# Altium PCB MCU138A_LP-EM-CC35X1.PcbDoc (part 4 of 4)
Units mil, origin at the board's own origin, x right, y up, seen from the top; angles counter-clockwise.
Board outline 2309.44 x 2672.36 mil, 4 copper layers (Top Layer, L02_GND, L03_PWR, Bottom Layer), stack 60 mil thick; 235 components, 167 nets, 678 pads, 887 vias.
Unrouted connection lines stored in the file: 19.
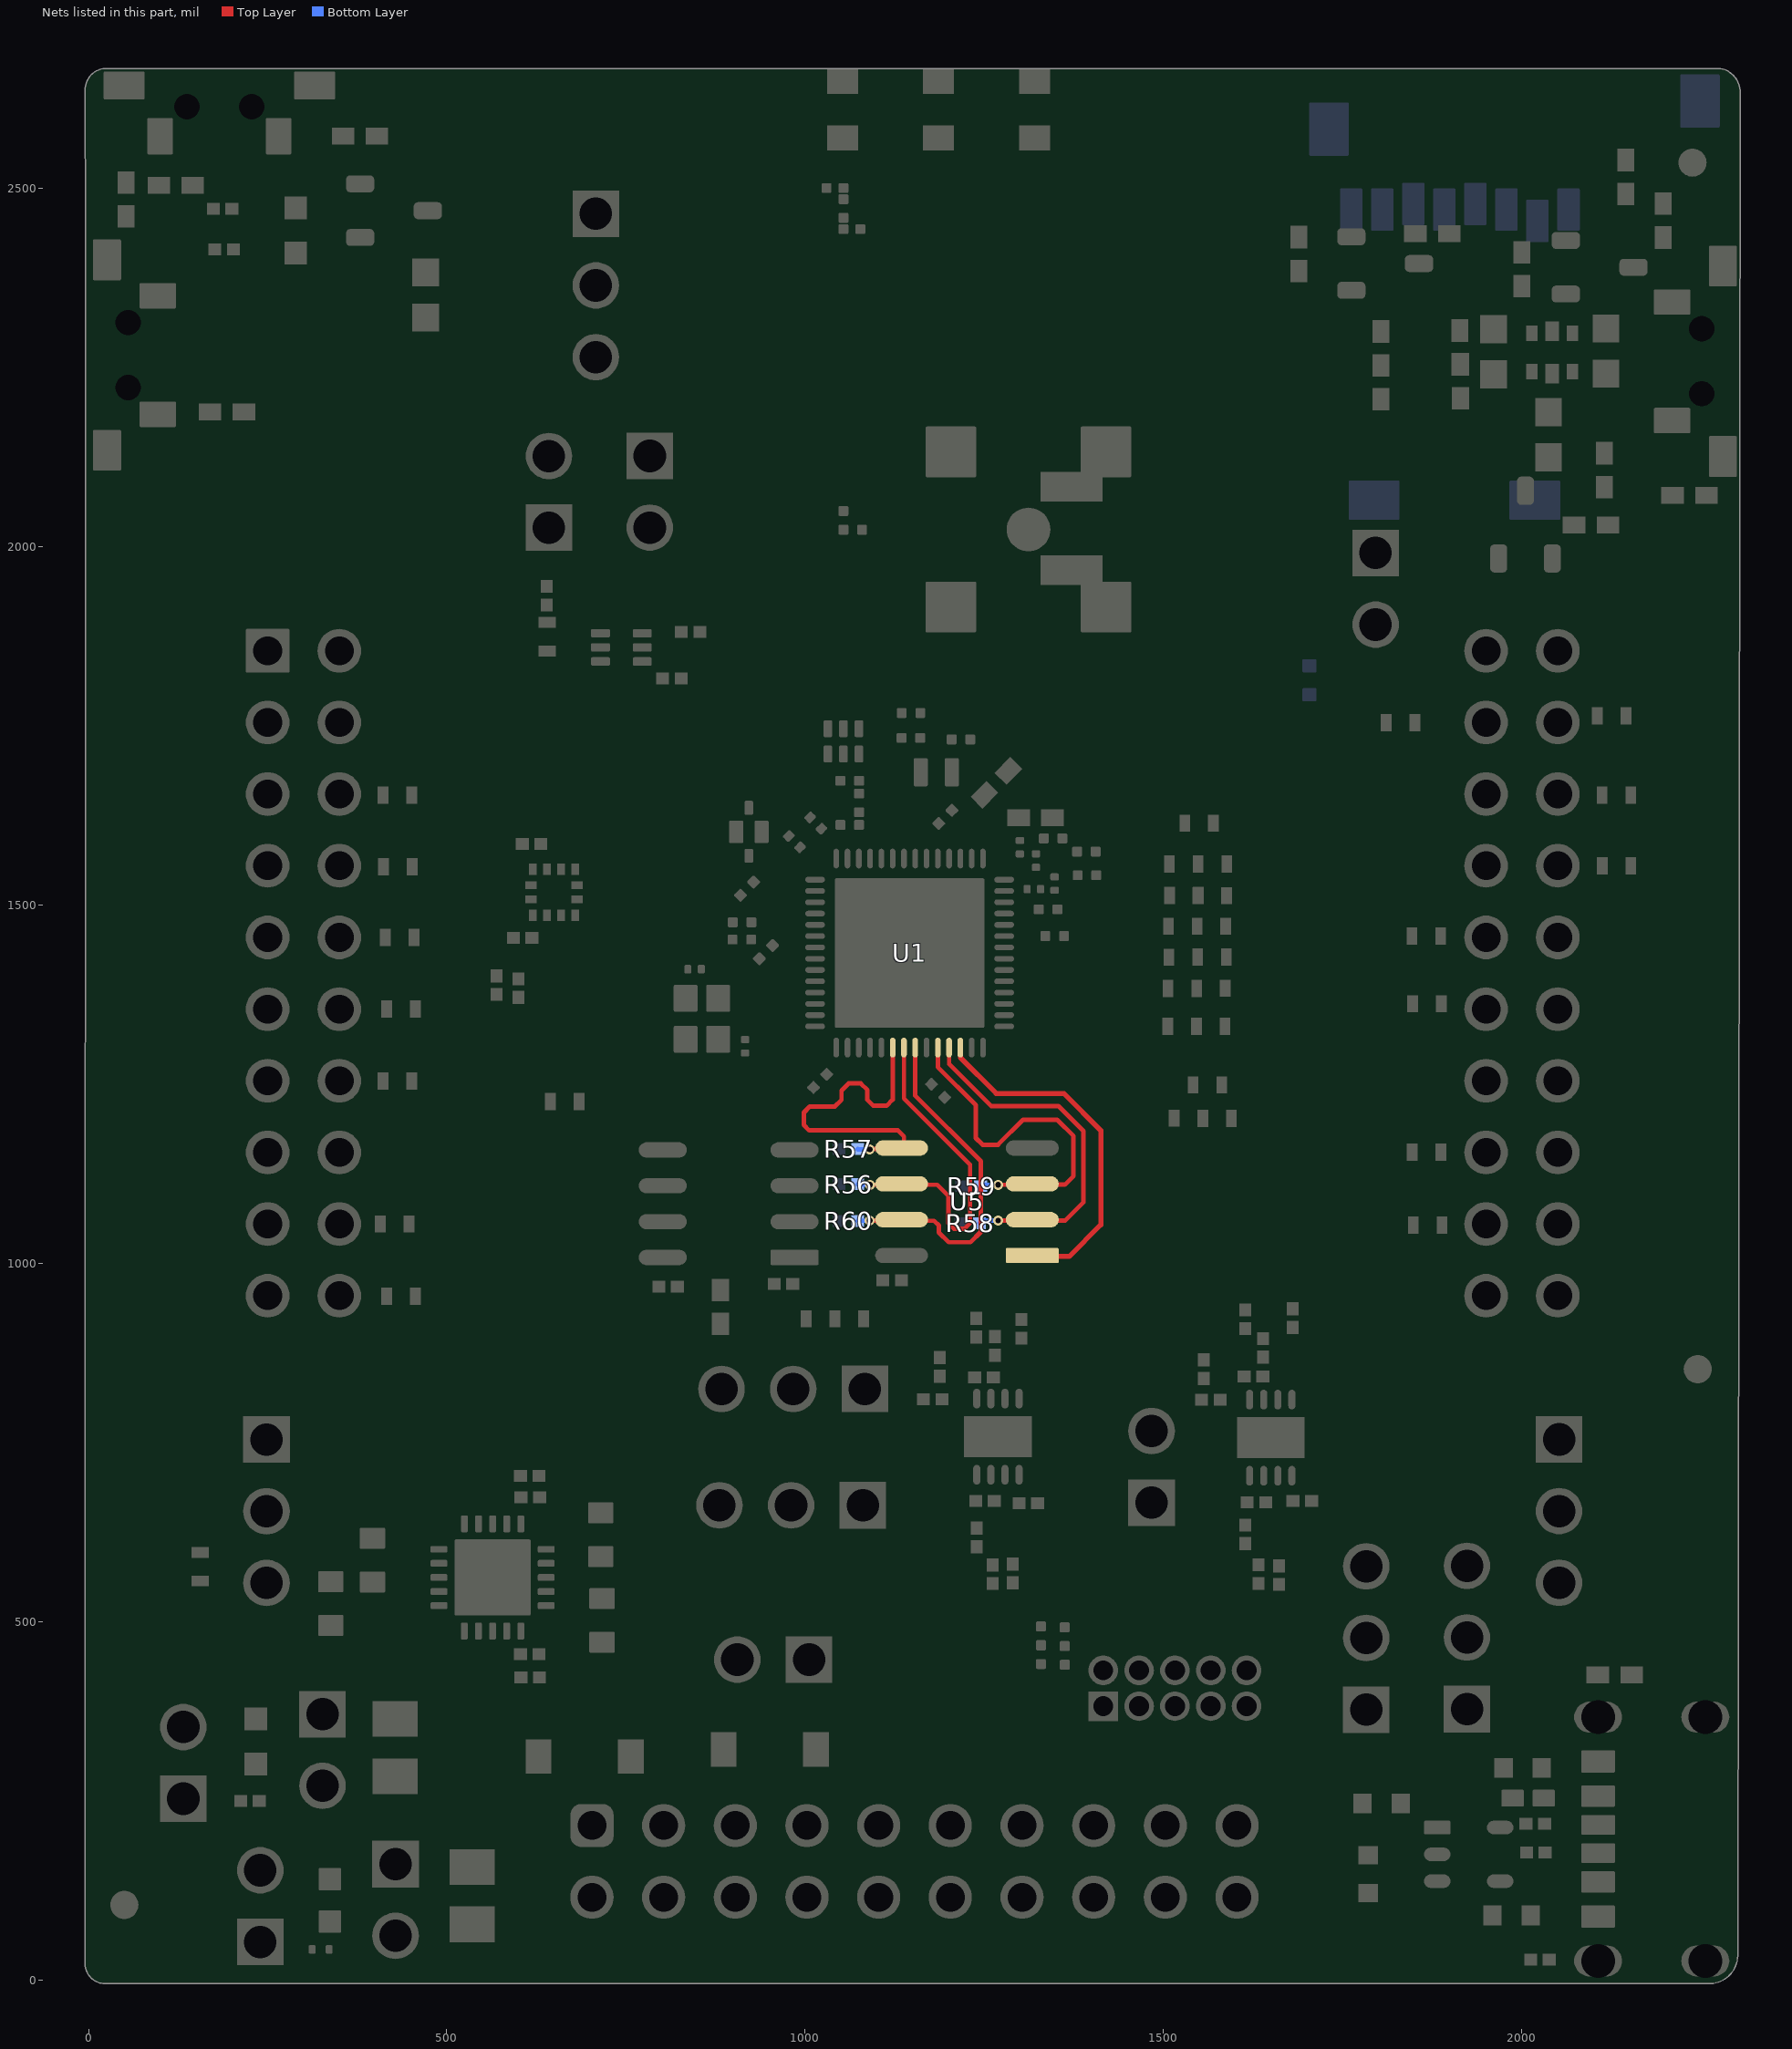
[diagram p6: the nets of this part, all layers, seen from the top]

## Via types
v1: diameter 14, hole 7.87, Top Layer to Bottom Layer, tented both sides, 816 vias
v2: diameter 19.68, hole 7.87, Top Layer to Bottom Layer, tented both sides, 25 vias
v3: diameter 14, hole 8, Top Layer to Bottom Layer, tented both sides, 19 vias
v4: diameter 24, hole 12, Top Layer to Bottom Layer, tented both sides, 14 vias
v5: diameter 19.68, hole 7.87, Top Layer to Bottom Layer, 13 vias

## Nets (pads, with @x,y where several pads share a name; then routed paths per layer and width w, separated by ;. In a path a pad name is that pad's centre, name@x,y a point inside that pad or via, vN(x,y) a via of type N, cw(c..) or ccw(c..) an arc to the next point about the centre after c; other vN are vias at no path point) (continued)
xSPI_CLK: R56.1 U1.21 U5.6 | length 489
  Top Layer w6.17: v1@1093,1109.71 1137.89,1109.71 1184.3,1109.71 1199.98,1094.03 1199.98,1055.81 1207.6,1048.19 1222.03,1048.19 1230.15,1056.31 1230.15,1137.88 1137.8,1230.22 U1.21@1137.8,1301.19
  Bottom Layer w6.17: R56.1@1073.16,1110.41 1073.5,1110.07 1090.07,1110.07 v1(1090.41,1109.73)
xSPI_CS_FLASH: U1.26 U5.1 | length 494.3
  Top Layer w7: U1.26@1216.54,1301.19 1216.54,1287.25 1266.64,1237.15 1360.89,1237.15 1412.58,1185.45 1412.58,1053.94 1368.36,1009.71 U5.1@1320.26,1009.71
xSPI_D0: R57.1 U1.20 U5.5 | length 489
  Top Layer w6.17: v1@1093,1159.71 1137.89,1159.71 1137.89,1177.3 1129.53,1185.66 1005.75,1185.66 998.14,1193.26 998.14,1210.64 1006.36,1218.86 1041.36,1218.86 1050.58,1228.08 1050.58,1241.17 1060.56,1251.15 1077.66,1251.15 1086.69,1242.12 1086.69,1228.32 1095.04,1219.97 1113.54,1219.97 1122.05,1228.48 U1.20@1122.05,1301.19
  Bottom Layer w6.17: R57.1@1073.15,1159.51 1073.4,1159.27 1089.86,1159.27 v1(1090.11,1159.02)
xSPI_D1: R58.1 U1.25 U5.2 | length 505.1
  Top Layer w6.17: U1.25@1200.79,1301.19 1200.79,1278.22 1259.41,1219.61 1353.22,1219.61 1388.3,1184.52 1388.3,1085.4 1362.86,1059.97 1320.52,1059.97 1320.26,1059.71 v1(1269.02,1059.71)
  Bottom Layer w6.17: R58.1@1243.14,1056.31 cw(c1251.36,1048.09) 1251.36,1059.71 v1(1269.02,1059.71)
xSPI_D2: R59.1 U1.24 U5.3 | length 502.9
  Top Layer w6.17: U1.24@1185.05,1301.19 1185.05,1273.92 1238.04,1220.92 1238.04,1175.02 1247.54,1165.52 1269.05,1165.52 1303.93,1200.4 1351.49,1200.4 1374.27,1177.62 1374.27,1122.07 1362.17,1109.96 1320.51,1109.96 1320.26,1109.71 v1(1269.02,1109.71)
  Bottom Layer w6.17: R59.1@1244.75,1107.86 cw(c1249.22,1103.4) 1249.22,1109.71 v1(1269.02,1109.71)
xSPI_D3: R60.1 U1.22 U5.7 | length 488.1
  Top Layer w6.17: v1@1093,1059.71 1137.89,1059.71 1138.05,1059.55 1179.89,1059.55 1186.48,1052.97 1186.48,1043.22 1200.13,1029.57 1230.64,1029.57 1245.02,1043.95 1245.02,1142.62 1153.55,1234.09 U1.22@1153.55,1301.19
  Bottom Layer w6.17: R60.1@1073.42,1059.43 1073.58,1059.59 1089.93,1059.59 v1(1090.09,1059.75)
pads on no net: E1.2 E1.3 E1.4 E1.5 FID1.1 FID2.1 FID3.1 J2.2@1371.62,2084.59 J2.3@1371.62,1966.48 J3.10 J7.2 J7.3 J7.4 J7.5 J7.9 J22.6 J22.8 LBL1.0 S1. SH-J1.0 SH-J2.0 SH-J3.0 SH-J4.0 SH-J5.0 SH-J6.0 SH-J7.0 SH-J8.0 SH-J9.0 SH-J10.0 SH-J11.0 SH-J12.0 SH-J13.0 SH-J14.0 SW1. SW2. U2.7 U2.9 U2.17 U2.19 U2.21A U2.21B U2.21C U2.21D U8.3 U9.4 U9.5 U9.6 U9.11

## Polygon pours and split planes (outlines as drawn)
GND on Top Layer "TOP_LAYER_GND_P000" (solid, remove dead copper, pour order 0): 22.54,2667.32 2277.75,2666.89 cw(c2273.98,2636.17) 2304.69,2632.31 2301.28,30.28 cw(c2258.62,38.22) 2262.2,-5.02 22.54,-5.05 cw(c23.83,23.48) -4.7,24.75 -4.43,2634.94 cw(c25.18,2637.7)
VDD_PA on L03_PWR "L03_PWR_VDD_PA_P024" (solid, remove dead copper, pour order 24): 89.12,323.4 335.95,323.4 ccw(c335.95,369.29) 381.84,369.29 381.84,1180.26 691.81,1490.22 1032.34,1490.22 1078.11,1535.99 1078.11,1641.26 995.79,1723.58 108.39,1723.58 89.12,1704.31
GND on L03_PWR "L03_PWR_GND_P035" (solid, remove dead copper, pour order 35): 22.5,2667.35 2277.71,2666.91 cw(c2273.94,2636.19) 2304.65,2632.34 2301.24,30.3 cw(c2258.58,38.25) 2262.16,-5 22.5,-5.03 cw(c23.79,23.5) -4.74,24.77 -4.47,2634.96 cw(c25.14,2637.73)
VCC_BRD_3V3 on L03_PWR "L03_PWR_VCC_BRD_3V3_P025" (solid, remove dead copper, pour order 25): 584.24,200.18 584.56,78.76 ccw(c629.39,78.88) 629.39,34.06 1122.84,34.06 1122.84,704.99 1041.35,701.09 1048.11,536.63 857.24,248.23
VBAT_CC_1V8 on L03_PWR "L03_PWR_VBAT_CC_1V8_P023" (solid, remove dead copper, pour order 23): 1292.25,1600.08 1285.1,1592.93 1271.9,1592.93 1245.35,1619.48 1218.7,1619.48 1202.38,1603.17 1202.38,1530.07 1139.92,1467.61 967.34,1467.61 949.52,1443.72 916.31,1443.72 916.31,1467.61 849.63,1467.61 793.59,1411.56 793.59,1192.51 646.96,1045.89 646.96,500.3 473.13,368.45 473.13,127.5 cw(c466.8,127.5) 466.8,121.17 400.59,121.17 cw(c400.59,132.45) 389.31,132.45 389.31,514.32 492.28,568.41 492.28,1217.18 815.28,1540.19 989.4,1540.19 1002.13,1552.92 1055.9,1552.92 1106.53,1605.88 1202.38,1701.73 1292.25,1701.73
VCC_BRD_1V8 on L03_PWR "L03_PWR_VCC_BRD_1V8_P030" (solid, remove dead copper, pour order 30): 189.77,78.26 189.77,40.27 ccw(c208.29,40.27) 208.29,21.75 543.92,21.75 ccw(c543.92,51.47) 573.63,50.73 578.14,232.14 682.05,246.54 927.93,429.03 927.93,874.37 920.03,882.27 917.4,879.63 813.86,879.63 813.86,658.54 482.23,360.05 484.85,232.14 482.23,94.79 292.97,94.79 206.3,94.79 ccw(c206.3,78.26)
VIO2_IN on L03_PWR "L03_PWR_VIO2_IN_P029" (solid, remove dead copper, pour order 29): 1052.45,987.82 1052.45,982.57 1065.48,969.25 1169.87,969.25 1169.98,869.78 1167.52,867.32 1039.05,867.32 1026.94,855.21 1026.94,796.08 1023.63,793.42 946.29,793.42 946.29,1137.51 1030.69,1284.65 1051.12,1284.65
VIO1_IN on L03_PWR "L03_PWR_VIO1_IN_P027" (solid, remove dead copper, pour order 27): 942.51,627.46 1041.4,627.46 1041.4,686.26 1354.39,680.72 1338.3,1504.72 1212.69,1504.72 1209.92,782.65 946.47,782.65 942.51,703.38
GND on L02_GND "L02_GND_GND_P034" (solid, remove dead copper, pour order 34): 22.5,2667.34 2277.71,2666.91 cw(c2273.94,2636.19) 2304.65,2632.33 2301.24,30.3 cw(c2258.58,38.24) 2262.16,-5 22.5,-5.03 cw(c23.79,23.5) -4.74,24.77 -4.47,2634.95 cw(c25.14,2637.72)
GND on Bottom Layer "BOTTOM_LAYER_GND_P036" (solid, remove dead copper, pour order 36): 22.5,2667.34 2277.71,2666.91 cw(c2273.94,2636.18) 2304.65,2632.33 2301.24,30.29 cw(c2258.58,38.24) 2262.16,-5.01 22.5,-5.03 cw(c23.79,23.49) -4.74,24.76 -4.47,2634.95 cw(c25.14,2637.72)

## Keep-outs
L03_PWR:
  region: 1565.66,541.8 1567.67,539.79 1567.67,535.19 1625.47,535.19 1634.03,521.13 ccw(c1637.55,523.27) 1641.49,522.08 1645.43,535.19 1690.75,580.51 1690.75,605.34 1633.22,547.82 1569,547.82 1564.88,543.69 ccw(c1565.66,542.9)
Keep-Out Layer:
  text ".Layer_Name" at 577.01,-720.69 h60

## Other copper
Top Layer:
  rectangle net GND: -4.41,2057.48 24.67,2452.89
  rectangle net GND: 2273.93,2045.34 2303.01,2440.75
  rectangle net NetFB4_1: 1995.18,18.97 2023.84,102.86
  rectangle net NetFB4_1: 2050.01,289.79 2129.55,323.85
  region net NetD5_1: 2041.77,242.32 2041.77,309.73 2014.49,309.73 2014.49,242.32
  rectangle net NetD5_1: 2014.43,241.53 2121.25,271.78
  region net NetFB1_1: 1850.87,214.65 1769,214.65 1769,160.12 1850.87,160.12
  region net XDS_5V: 1810.21,32.02 1810.21,135.5 1755.67,135.5 1755.67,32.02
  rectangle net NetD8_2: 1887.46,274.76 1987.96,329.3
  rectangle net VBAT_CC_1V8: 396.28,128.2 568.4,194.01
  rectangle net VCC_BRD_1V8: 395.39,29.88 566.63,104.43
  rectangle net VCC_BRD_3V3: 293.41,239.19 460.66,309.65
  rectangle net VDD_PA: 294.3,338.2 459.32,403.31
  rectangle net NetC4_2: 627.11,576.88 785.8,606.69
  rectangle net NetC5_2: 626.42,516.8 785.11,546.61
  rectangle net VCC_BRD_5V: 110.74,541.43 468.24,569.93
  rectangle net VCC_LP_5V: 103.64,581.18 170.6,618.8
  rectangle net GND: 1046.48,2481.11 1060.3,2501.65
  rectangle net NetC9_1: 1046.53,2442.81 1060.32,2463.34
  region net GND: 1073.79,2649.71 1030.48,2649.71 1030.48,2533.57 1073.79,2533.57
  region net GND: 930.36,2637.33 930.36,2665.75 cw(c931.77,2665.75) 931.77,2667.16 994.75,2667.16 cw(c994.79,2665.37) 996.57,2665.37 996.58,2637.63
  pour cut-out: 1428.72,2062.86 cw(c1418.85,2051.68) 1433.76,2051.68 1433.76,1995.49 cw(c1421.44,1995.49) 1430.15,1986.78 1428.76,1985.38 1328.56,1985.38 1328.56,2062.86
  pour cut-out: 1093.57,1632.43 1093.68,1663.27 1086.9,1663.27 1086.9,1632.43
  region net Diplexer_A_IN: 1068.32,1671.46 1068.32,1656.73 1068.83,1656.22 1081.41,1656.22 1082.02,1656.83 1082.02,1670.29 1080.84,1671.47 1080.82,1671.44 1068.46,1671.44
  region net RF_A: 1068.27,1629.37 1068.27,1614.64 1068.78,1614.13 1081.36,1614.13 1081.97,1614.74 1081.97,1628.2 1080.79,1629.38 1080.77,1629.35 1068.41,1629.35
  region net VCC_BRD_5V: 529.9,650.3 459.9,650.3 458.63,650.3 451.62,650.3 451.62,476.3 530.9,476.3 530.9,501.3 502.9,501.3 501.9,502.3 501.9,552.3 471.58,552.3 471.58,574.3 501.9,574.3 501.9,625.3 529.9,625.3
  pour cut-out: 1061.01,1623.05 1061.12,1653.9 1054.34,1653.9 1054.34,1623.05
  pour cut-out: 1073.65,2432.37 1073.95,2511.56 1032.64,2511.56 1032.64,2432.37
  pour cut-out: 1039.43,2018.93 1039.54,2049.77 1032.76,2049.77 1032.76,2018.93
  pour cut-out: 1410.15,2491.88 1089.29,2491.88 1089.29,2511.56 996.77,2511.56 996.77,2667.08 1410.15,2667.08
  region net VDD_PA: 1025.98,1615.41 1022.2,1615.41 1013.36,1606.56 1013.36,1601.75 1037.27,1577.84 1037.27,1555.17 1041.27,1551.15 1060.32,1551.14 1061.34,1551.14 1063.52,1553.33 1063.52,1577.86
  region net VBAT_CC_1V8: 1200.24,1614.42 1188.01,1626.66 1186.38,1626.73 1165.36,1605.71 1165.36,1553.49 1167.67,1551.19 1170.93,1551.19 1173.24,1553.49 1173.24,1587.41
  region net DIG_LDO_OUT: 1231.14,1636.96 1231.14,1652.8 1252.72,1674.38 1255.83,1674.38 1270.52,1659.69 1270.52,1656.81 1248.48,1634.76 1248.48,1631.2 1241.01,1623.65 1232.37,1623.65 1189.02,1580.29 1189.02,1554.27 1189.06,1552.77 1187.51,1551.23 1182.91,1551.23 1181.03,1553.11 1181.03,1586.85
  region net VBAT_CC_1V8: 1288.46,1639.33 1256.05,1606.93 1238.24,1606.93 1211.75,1580.44 1211.75,1552.5 1213.02,1551.23 1218.51,1551.23 1220.9,1553.62 1220.9,1577.39 1240.08,1596.56 1279.04,1596.56 1284.5,1602.02 1305.91,1602.02 1311.86,1607.9 1314.73,1610.76 1314.73,1635.71 1311.11,1639.33
  region net VIO1_IN: 1267.88,1452.51 1304.69,1452.51 1309.85,1447.35 1344.84,1447.35 1344.84,1465.32 1322.22,1465.32 1318.79,1461.89 1265.29,1461.89 1263.82,1460.42 1263.82,1454.51 1265.82,1452.51
  region net VDD_SF_IN: 1178.58,1261.15 1189.25,1250.48 1189.25,1248.16 1176.88,1235.79 1175.91,1235.79 1162.42,1249.28 1162.42,1281.65 1163.95,1283.18 1163.95,1312.53 1166.4,1314.97 1171.95,1314.97 1173.53,1313.39 1173.53,1275.1 1178.58,1270.05
  pour cut-out: 1250.01,1437.22 1250.01,1328.74 1041.35,1328.74 1041.35,1537.41 1250.01,1537.41 1250.01,1444.62 1263.79,1444.62 1263.79,1551.19 1027.57,1551.19 1027.57,1314.97 1263.79,1314.97 1263.79,1437.22
  region net VIO2_IN: 1047.75,1267.19 1030.1,1249.54 1028.21,1249.54 1017.19,1260.56 1017.19,1268.74 1038.63,1290.18 1038.63,1313.4 1040.29,1314.89 1045.69,1314.89 1047.76,1312.82 1047.76,1311.29 1047.75,1311.12
  pour cut-out: 846.83,1443.18 846.83,1486.5 911.77,1486.5 911.77,1443.18
  region net VBAT_CC_1V8: 995.91,1492.37 1024.68,1492.37 1027.4,1489.66 1027.4,1470.65 1024.87,1468.12 1014.81,1468.12 959.95,1468.12 935.22,1443.39 915.79,1443.39 915.25,1443.94 915.25,1483.56 916.47,1484.77 951.19,1484.77 988.31,1484.77
  region net PA_LDO_OUT: 1027.57,1556.89 995.93,1588.53 992.29,1588.53 984.53,1580.77 984.53,1574.07 999.57,1559.02 999.57,1533.87 1002.16,1531.5 1025.26,1531.5 1027.57,1533.81
  pour cut-out: 1185.77,2007.87 1185.89,2038.72 1179.1,2038.72 1179.1,2007.87
  text ".Layer_Name" at 577.01,-720.69 h60
L02_GND:
  pour cut-out: 1185.18,2065.06 1267.28,2065.06 1269.52,2067.3 cw(c1311.06,2025.76) 1311.06,2084.51 1327.8,2084.51 1327.8,2062.95 1420.21,2062.95 cw(c1420.21,2054.64) 1426.08,2060.51 1426.53,2060.06 cw(c1419.57,2053.1) 1429.41,2053.1 1429.41,1996.91 cw(c1416.98,1996.96) 1425.74,1988.13 1424.41,1986.8 1424.41,1985.08 1414.41,1985.08 1414.41,1988.14 1327.8,1988.14 1327.8,1966.58 1311.06,1966.58 cw(c1311.06,2025.3) 1269.53,1983.78 1267.53,1985.78 1266.45,1985.78 1185.18,1985.78
  pour cut-out: 1410.15,2491.88 1089.29,2491.88 1089.29,2511.56 996.77,2511.56 996.77,2667.08 1410.15,2667.08
L03_PWR:
  region net VCC_BRD_3V3: 89.82,299.89 89.82,228.29 ccw(c107.5,228.29) 107.5,210.61 365.11,210.61 ccw(c365.11,220.71) 375.21,220.71 375.21,295.66 ccw(c362.32,295.66) 362.32,308.54 98.47,308.54 ccw(c98.47,299.89)
  pour cut-out: 1410.15,2491.88 1089.29,2491.88 1089.29,2511.56 996.77,2511.56 996.77,2667.08 1410.15,2667.08
Bottom Layer:
  pour cut-out: 1410.15,2491.88 1089.29,2491.88 1089.29,2511.56 996.77,2511.56 996.77,2667.08 1410.15,2667.08
  region net GND: 1081.89,1326.71 1240.33,1326.71 1252.11,1338.49 1252.11,1532.73 1245.63,1539.21 1041.5,1539.21 1039.07,1536.78 1039.07,1332.5 1044.84,1326.73 1081.63,1326.73
  text ".Layer_Name" at 577.01,-720.69 h60

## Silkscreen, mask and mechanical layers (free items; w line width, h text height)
Top Overlay:
  circle w10: c2010.28,2326.75 r2.47
  region: -3.06,757.98 -3.06,712.48 137.69,712.48 183.44,758.23 138.94,803.23 -3.06,803.23 -3.06,757.98 4.94,757.98 4.94,795.23 4.44,795.73 135.94,795.73 172.94,758.48 172.94,757.48 135.94,720.48 4.94,720.48 4.94,757.98
  region: -3.06,656.84 -3.06,611.34 137.69,611.34 183.44,657.09 138.94,702.09 -3.06,702.09 -3.06,656.84 4.94,656.84 4.94,694.09 4.44,694.59 135.94,694.59 172.94,657.34 172.94,656.34 135.94,619.34 4.94,619.34 4.94,656.84
  region: 2301.23,752.98 2301.23,798.48 2160.48,798.48 2114.73,752.73 2159.23,707.73 2301.23,707.73 2301.23,752.98 2293.23,752.98 2293.23,715.73 2293.73,715.23 2162.23,715.23 2125.23,752.48 2125.23,753.48 2162.23,790.48 2293.23,790.48 2293.23,752.98
  region: 2301.23,654.6 2301.23,700.1 2160.48,700.1 2114.73,654.35 2159.23,609.35 2301.23,609.35 2301.23,654.6 2293.23,654.6 2293.23,617.35 2293.73,616.85 2162.23,616.85 2125.23,654.1 2125.23,655.1 2162.23,692.1 2293.23,692.1 2293.23,654.6
  region: 2301.3,555.48 2301.3,599.98 2159.8,599.98 2114.8,554.98 2159.3,509.98 2301.3,509.98 2301.3,555.48 2285.71,555.48 2285.71,524.41 2165.16,524.41 2165.16,581.48 2285.71,581.48 2285.71,555.48
  region: -1.07,553.21 -1.07,508.71 140.43,508.71 185.43,553.71 140.93,598.71 -1.07,598.71 -1.07,553.21 37.93,553.21 37.93,579.21 118.43,579.21 118.43,527.21 37.93,527.21 37.93,553.21
  lines w10: 1624.68,1940.33 1670.18,1940.14 ; 1624.99,2126.51 1697.11,2126.21 ; 1625.25,1941.04 1625.25,2125.34 ; 1658.76,1923.81 1673.93,1938.86 ; 1658.99,1956.99 1674.94,1941.04 ; 1702.65,2063.36 1703.28,2213 1762.43,2212.76 1762.19,2213 1778.17,2212.93 ; 1704.05,2063.29 1776.17,2062.99
  text "'.PRJ_Number'.PCB_Rev" at 606.62,2624.67 h30
  text "RST" at 370.57,2619.91 h30
  text "LP-EM-CC35X1" at 1500.16,2601.53 h50
  text "Rev A" at 1497.69,2518.14 h50
  text "PU" at 780.81,2448.62 h30
  text "RST" at 777.76,2345.22 h30
  text "LP" at 774.72,2250.19 h30
  text "Green->P14" at 1723.42,2158.36 h30
  text "Red->P9" at 1723.42,2116.67 h30
  text "Blue->P8" at 1722.72,2075.57 h30
  text "LED EN" at 1718.61,1873.92 h30 r90
  text "P53" at 1817.42,1796.06 h30
  text "P43" at 1720.87,1739.71 h30
  text "P51" at 131.96,1737.27 h30
  text "P44" at 2168.89,1735.73 h30
  text "P27" at 1761.8,1641.49 h30
  text "P41" at 477.91,1640.31 h30
  text "P19" at 2168.93,1639.34 h30
  text "P28" at 120.04,1633.58 h30
  text "P42" at 469.43,1553.55 h30
  text "P30" at 1759.46,1544.44 h30
  text "P14" at 2172.23,1536.84 h30
  text "P29" at 123.36,1532.58 h30
  text "P43" at 465.47,1450.71 h30
  text "P42" at 1752.29,1443.45 h30
  text "P36" at 120.66,1437.75 h30
  text "RST" at 2172.23,1435.72 h30
  text "P46" at 474.13,1346.79 h30
  text "P35" at 116.67,1341.36 h30
  text "P16" at 2168.89,1332.94 h30
  text "P41" at 1757.56,1328.7 h30
  text "LOG" at 1755.01,1243.47 h30
  text "P17" at 2169.72,1241.85 h30
  text "P19" at 463.01,1238.48 h30
  text "P18" at 118.46,1236.55 h30
  text "P8" at 1775.72,1143.15 h30
  text "P32" at 115.57,1139.07 h30
  text "P33" at 2172.23,1139.06 h30
  text "P16" at 463.16,1128.87 h30
  text "P14" at 470.04,1041.76 h30
  text "P34" at 2178.08,1039.61 h30
  text "P14" at 1764.14,1036.97 h30
  text "P11" at 119.36,1034.15 h30
  text "P8" at 477.12,946.58 h30
  text "P31" at 2181.42,941.84 h30
  text "P9" at 1771.11,934.32 h30
  text "P12" at 115.67,928.81 h30
  text "P13" at 476.13,898.08 h30
  text "VIO2" at 692.63,818.51 h35
  text "GND" at 7.42,736.14 h72.83
  text "GND" at 2148.98,728.23 h72.83
  text "1V8" at 849.99,725.88 h30
  text "3V3" at 1054.21,724.51 h30
  text "VIO1" at 706.05,672.26 h35
  text "GND" at 7.42,635.01 h72.83
  text "GND" at 2148.98,629.85 h72.83
  text "OPAMP EN" at 1411.35,609.85 h30 r90
  text "3V3" at 2169.9,530.32 h72.83
  text "5V" at 39.19,528.88 h72.83 r0.33
  text "TX" at 1912.74,281.04 h30
  text "RX" at 1759.62,279.74 h30
  text "3V3" at 57.33,261.78 h40 r90
  text "1V8" at 155.87,72.55 h40 r90
  text ".Layer_Name" at 577.01,-720.69 h60
Bottom Overlay:
  region: 2300.91,652.79 2300.91,698.29 2160.16,698.29 2114.41,652.54 2158.91,607.54 2300.91,607.54 2300.91,652.79 2292.91,652.79 2292.91,615.54 2293.41,615.04 2161.91,615.04 2124.91,652.29 2124.91,653.29 2161.91,690.29 2292.91,690.29 2292.91,652.79
  region: -2.59,756.92 -2.59,711.42 138.16,711.42 183.91,757.17 139.41,802.17 -2.59,802.17 -2.59,756.92 5.41,756.92 5.41,794.17 4.91,794.67 136.41,794.67 173.41,757.42 173.41,756.42 136.41,719.42 5.41,719.42 5.41,756.92
  region: -2.59,656.92 -2.59,611.42 138.16,611.42 183.91,657.17 139.41,702.17 -2.59,702.17 -2.59,656.92 5.41,656.92 5.41,694.17 4.91,694.67 136.41,694.67 173.41,657.42 173.41,656.42 136.41,619.42 5.41,619.42 5.41,656.92
  region: -1.57,553.45 -1.57,508.95 139.93,508.95 184.93,553.95 140.43,598.95 -1.57,598.95 -1.57,553.45 37.43,553.45 37.43,579.45 117.93,579.45 117.93,527.45 37.43,527.45 37.43,553.45
  region: 2300.91,752.79 2300.91,798.29 2160.16,798.29 2114.41,752.54 2158.91,707.54 2300.91,707.54 2300.91,752.79 2292.91,752.79 2292.91,715.54 2293.41,715.04 2161.91,715.04 2124.91,752.29 2124.91,753.29 2161.91,790.29 2292.91,790.29 2292.91,752.79
  region: 2300.57,555.27 2300.57,599.77 2159.07,599.77 2114.07,554.77 2158.57,509.77 2300.57,509.77 2300.57,555.27 2279.07,555.27 2279.07,529.27 2163.07,529.27 2163.07,581.27 2279.07,581.27 2279.07,555.27
  text "GND" at 147.64,734.2 h72.83
  text "GND" at 2288.99,730.68 h72.83 r0.59
  text "GND" at 147.64,634.2 h72.83
  text "GND" at 2288.99,630.68 h72.83 r0.59
  text "5V" at 115.49,530.78 h72.83 r0.31
  text "3V3" at 2280.01,530.42 h72.83
  text ".Layer_Name" at 577.01,-720.69 h60
Top Paste:
  text ".Layer_Name" at 577.01,-720.69 h60
Bottom Paste:
  text ".Layer_Name" at 577.01,-720.69 h60
Top Solder:
  pour cut-out: 1180.23,1892.18 1154.49,1892.18 1154.49,1943.24 1180.23,1943.24
  text ".Layer_Name" at 577.01,-720.69 h60
  text ".Layer_Name" at 577.01,-720.69 h60
Bottom Solder:
  text ".Layer_Name" at 577.01,-720.69 h60
Drill Guide:
  text ".Layer_Name" at 577.01,-720.69 h60
M1 Board Outline:
  lines w10: -4.7,177.37 -4.11,19.34 ; -4.11,18.93 ccw(c16.17,18.93) 16.17,-1.34 2260.8,-5.28 ccw(c2260.8,38.39) 2304.47,38.39 2304.73,2624.02 ccw(c2261.42,2624.02) 2261.42,2667.33 20.89,2666.56 ccw(c20.89,2641.56) -4.11,2641.56 -4.11,18.93
  text ".Layer_Name" at 577.01,-720.69 h60
M2 Board Dimensions:
  rectangle: 2519.69,-19.09 2644.69,105.91
  rectangle: 2644.69,-144.09 3019.69,-19.09
  lines w7: 2519.69,-19.09 3519.69,-19.09 ; 2644.69,-144.09 2644.69,105.91 ; 2769.69,-144.09 2769.69,105.91 ; 3019.69,-144.09 3019.69,105.91 ; 3269.69,-144.09 3269.69,105.91 ; 2519.69,-144.09 3519.69,-144.09 3519.69,105.91 2519.69,105.91 2519.69,-144.09
  text ".Layer_Name" at 577.01,-720.69 h60
M3 3D STEP Top:
  text ".Layer_Name" at 577.01,-720.69 h60
M4 3D STEP Bottom:
  text ".Layer_Name" at 577.01,-720.69 h60
M5 Assembly Top:
  lines w10: -291.99,-792.37 6308.01,-792.37 ; -291.99,-589.03 6310.01,-589.03 ; -291.99,-385.7 -291.99,-995.7 3713.01,-995.7 6310.01,-995.7 6310.01,-385.7 -291.49,-385.7 -291.49,-995.7 1284.01,-995.7 ; 2173.01,-995.7 2173.01,-385.7 ; 3440.01,-589.03 3440.01,-385.7 ; 4280.01,-589.03 4280.01,-385.7 ; 4902.01,-1002.2 4902.01,-799.37
  text "ASSEMBLY VARIANT:" at 3584.11,107.34 h60
  text ".VariantName" at 4620.11,107.34 h60
  text "COMPONENTS MARKED 'DNP' SHOULD NOT BE POPULATED." at 3592.53,-39.37 h60
  text "PCB VIEWED FROM TOP SIDE" at -228.49,-517.87 h60
  text "BOARD #:" at 2248.01,-517.87 h60
  text ".PRJ_Number" at 2793.51,-517.87 h60
  text "REV:" at 3638.01,-517.87 h60
  text ".PCB_Rev" at 3929.51,-517.87 h60
  text "SVN REV:" at 4476.01,-517.87 h60
  text ".VersionControl_RevNumber" at 4982.01,-517.87 h60
  text "TID #:" at 2248.01,-721.2 h60
  text ".TID" at 2793.51,-721.2 h60
  text "PLOT NAME =" at -228.49,-926.54 h60
  text ".plot_File_Name" at 577.01,-926.54 h60
  text "GENERATED    :" at 2250.01,-926.54 h60
  text ".Print_Date" at 3119.51,-926.54 h60
  text ".Print_Time" at 3848.51,-926.54 h60
  text "TEXAS INSTRUMENTS" at 5113.01,-926.54 h60
M6 Assembly Bottom:
  lines w10: -292.49,-589.53 6309.51,-589.53 ; -290.49,-792.87 6309.51,-792.87 ; 1115.51,-1002.7 1115.51,-799.87 ; 1737.51,-589.53 1737.51,-386.2 ; 2577.51,-589.53 2577.51,-386.2 ; 3844.51,-996.2 3844.51,-386.2 ; 4733.51,-996.2 6309.01,-996.2 6309.01,-386.2 -292.49,-386.2 -292.49,-996.2 2304.51,-996.2 6309.51,-996.2 6309.51,-386.2
  text "COMPONENTS MARKED 'DNP' SHOULD NOT BE POPULATED." at 6374.01,-177.16 h60
  text ".VariantName" at 5058.01,-296.2 h60
  text "ASSEMBLY VARIANT:" at 6097.01,-296.2 h60
  text ".VersionControl_RevNumber" at 1035.51,-518.37 h60
  text "SVN REV:" at 1541.51,-518.37 h60
  text ".PCB_Rev" at 2088.01,-518.37 h60
  text "REV:" at 2379.51,-518.37 h60
  text ".PRJ_Number" at 3224.01,-518.37 h60
  text "BOARD #:" at 3769.51,-518.37 h60
  text "PCB VIEWED FROM BOTTOM SIDE" at 6246.01,-518.37 h60
  text ".TID" at 3224.01,-721.7 h60
  text "TID #:" at 3769.51,-721.7 h60
  text "TEXAS INSTRUMENTS" at 904.51,-927.04 h60
  text ".Print_Time" at 2169.01,-927.04 h60
  text ".Print_Date" at 2898.01,-927.04 h60
  text "GENERATED    :" at 3767.51,-927.04 h60
  text ".plot_File_Name" at 5440.51,-927.04 h60
  text "PLOT NAME =" at 6246.01,-927.04 h60
M9 Title Sheet:
  drawing of 57 lines, arcs and shapes, not listed
  text "1" at 739.84,8174.3 h70
  text "2" at 3235.51,8174.3 h70
  text "3" at 5724.85,8174.3 h70
  text "4" at 8231.52,8174.3 h70
  text "5" at 10730.51,8174.3 h70
  text "6" at 13235.51,8174.3 h70
  text "A" at -416.49,7031.3 h70
  text "A" at 14383.51,7031.3 h70
  text "B" at -416.49,4651.3 h70
  text "B" at 14383.51,4651.3 h70
  text "C" at -416.49,2276.3 h70
  text "C" at 14383.51,2276.3 h70
  text "PROJECT TITLE:" at 11343.51,415.3 h45
  text ".PRJ_Title" at 11393.51,281.97 h70
  text "DESIGNED FOR:" at 11343.51,114.3 h45
  text ".PRJ_Customer" at 11393.51,-25.7 h70
  text "D" at -416.49,-93.7 h70
  text "D" at 14383.51,-93.7 h70
  text "FILE NAME:" at 11343.51,-185.7 h45
  text ".PCB_File_Name_No_Path" at 11393.51,-305.7 h70
  text "Texas Instruments (TI) and/or its licensors do not warrant the accuracy or completeness of this specification" at 6374.01,-467.54 h45
  text "ENGINEER:" at 11343.51,-475.7 h45
  text "LAYOUT BY:" at 12848.51,-475.7 h45
  text "or any information contained therein. TI and/or its licensors do not warrant that this design will meet" at 6329.02,-580.2 h45
  text ".PRJ_Engineer" at 11393.51,-630.69 h70
  text ".PCB_Layout" at 12899.01,-630.69 h70
  text "the specifications, will be suitable for your application or fit for any particular purpose, or will operate in" at 6329.02,-692.87 h45
  text ".Layer_Name" at 577.01,-720.69 h60
  text "ALTIUM DESIGNER VERSION:" at 12848.51,-785.7 h45
  text "an implementation. TI and/or its licensors do not warrant that the design is production worthy. You should" at 6329.02,-805.53 h45
  text "completely validate and test your design implementation to confirm the system functionality for your application." at 6374.01,-918.2 h45
  text ".print_Scale" at 11393.51,-919.03 h70
  text ".Application_BuildNumber" at 12899.01,-919.03 h70
  text "1" at 739.84,-1125.7 h70
  text "2" at 3235.51,-1125.7 h70
  text "3" at 5724.85,-1125.7 h70
  text "4" at 8231.52,-1125.7 h70
  text "5" at 10730.51,-1125.7 h70
  text "6" at 13235.51,-1125.7 h70
M10 Fab Notes:
  drawing of 189 lines, arcs and shapes, not listed
  text "DESIGN INFORMATION" at 12382.02,6493.97 h60
  text "MIN. TRACK WIDTH:" at 11737.47,6361.85 h60
  text "5" at 12833.71,6361.85 h60
  text "MIL" at 12988.47,6361.85 h60
  text "4" at 12834.17,6241.05 h60
  text "MIN. CLEARANCE:" at 11737.47,6237.72 h60
  text "MIL" at 12988.47,6237.72 h60
  text "MIN. VIA PAD SIZE:" at 11737.47,6113.6 h60
  text "14" at 12803.72,6113.6 h60
  text "MIL" at 12988.47,6113.6 h60
  text "0.05mm (2MIL)" at 12432.47,5983.7 h60
  text "MINIMUM ANNULAR RING" at 11408.23,5975.47 h60
  text "EXTERNAL" at 13140.47,5975.47 h60
  text "PER" at 11608.23,5865.35 h60
  text "IPC-D-275 CLASS 2 LEVEL C" at 11828.23,5865.34 h60
  text "MIL, HOLES" at 13316.47,5764.87 h60
  text "+/-" at 12924.01,5756.28 h60
  text "+/-" at 13778.01,5756.28 h60
  text "REGISTRATION TOLERANCES:" at 11408.23,5755.22 h60
  text "METAL" at 12608.01,5755.22 h60
  text "5" at 13184.21,5755.22 h60
  text "3" at 14017.21,5755.22 h60
  text "MIL" at 14133.47,5755.22 h60
  text "HOLE SIZE TOLERANCE (UNLESS OTHERWISE SPECIFIED):" at 11408.23,5656.9 h60
  text "+/-" at 13778.01,5654.03 h60
  text "3" at 14017.21,5652.97 h60
  text "MIL" at 14133.47,5652.97 h60
  text "MATERIAL:" at 11333.47,5515.32 h60
  text "FR-4 High Tg" at 12319.91,5386.8 h60
  text "X" at 12175.47,5378.81 h60
  text "FR-4" at 11754.47,5374.29 h60
  text "OTHER" at 13242.47,5374.29 h60
  text "62 MIL (1.6mm) +/-10%" at 12074.57,5231.26 h60
  text "X" at 11954.47,5228.81 h60
  text "THICKNESS:" at 11408.23,5223.04 h60
  text "OTHER" at 13359.47,5223.04 h60
  text "TOLERANCE:" at 11408.23,5084.72 h60
  text "X" at 12256.47,5084.72 h60
  text "ANSI IPC-6012 TYPE 3 CLASS 2" at 12434.48,5084.72 h60
  text "OTHER +/-" at 12434.47,4940.53 h60
  text "BOW & TWIST:" at 11408.23,4795.34 h60
  text "X" at 12256.47,4795.34 h60
  text "ANSI IPC-6012 TYPE 3 CLASS 2" at 12434.48,4795.34 h60
  text "OTHER +/-" at 12434.47,4648.65 h60
  text "DRILLING:" at 11333.47,4518.03 h60
  text "NC_DRILL FILES" at 13094.47,4412.84 h60
  text "REFERENCE:" at 11408.23,4408.9 h60
  text "X" at 12065.47,4408.81 h60
  text "AS SHOWN" at 12243.47,4408.9 h60
  text "X" at 12966.47,4408.9 h60
  text "OTHER" at 13392.47,4266.65 h60
  text "PTH COPPER THICKNESS:" at 11407.91,4263.12 h60
  text "X" at 12547.15,4263.12 h60
  text "20-30 um" at 12675.14,4263.12 h60
  text "BOARD FINISH:" at 11333.47,4115.53 h60
  text "SILKSCREEN:" at 11488.69,4005.4 h60
  text "X" at 12446.47,4005.4 h60
  text "TOP" at 12563.47,4005.4 h60
  text "X" at 12956.47,4005.4 h60
  text "BOTTOM" at 13074.47,4005.4 h60
  text "SILKSCREEN COLOR:" at 11488.69,3850.21 h60
  text "X" at 12445.47,3850.21 h60
  text "WHITE" at 12563.47,3850.21 h60
  text "OTHER" at 13074.47,3850.21 h60
  text "X" at 13171.57,3715.39 h60
  text "GREEN" at 12694.47,3706.76 h60
  text "OTHER" at 13312.47,3706.76 h60
  text "RED" at 13660.37,3704.6 h60
  text "SOLDER RESIST COLOR:" at 11488.69,3699.9 h60
  text "X" at 12576.47,3552.51 h60
  text "MATTE" at 12694.47,3552.51 h60
  text "SEMI-GLOSS" at 13312.01,3551.87 h60
  text "IMMERSION GOLD (ENIG)" at 12394.47,3379.74 h60
  text "ENEPIG" at 13732.01,3372.52 h60
  text "SURFACE FINISH:" at 11333.47,3371.52 h60
  text "X" at 12216.47,3371.52 h60
  text "IMM. TIN/SILVER OR EQUIV" at 11663.01,3234.2 h60
  text "OTHER" at 13094.47,3230.27 h60
  text "ARRAY/PANEL:" at 11333.47,3074.89 h60
  text "CUT AND TRIM PER M1 BOARD OUTLINE" at 12394.47,3066.67 h60
  text "X" at 12211.56,2933.83 h60
  text "N.C. ROUTE" at 12394.47,2930.7 h60
  text "V. SCORE" at 13260.47,2930.7 h60
  text "CERTIFICATION:" at 11333.47,2801.57 h60
  text "MATERIALS AND WORKMANSHIP FOR ALL PCBS" at 12058.47,2801.57 h60
  text "TO MEET OR EXCEED THE REQUIREMENTS OF:" at 12058.47,2707.51 h60
  text "X" at 11695.98,2578.88 h60
  text "ANSI IPC-A-600F CLASS ->" at 11823.97,2578.88 h60
  text "X" at 13471.98,2578.88 h60
  text "2" at 13581.97,2578.88 h60
  text "1" at 13266.97,2577.38 h60
  text "3" at 13935.97,2577.38 h60
  text "X" at 12507.98,2431.19 h60
  text "RoHS" at 12635.97,2431.19 h60
  text "OTHER" at 13280.37,2431.19 h60
  text "PER ORDER" at 13677.43,2431.19 h60
  text "ALL BOARDS MUST MEET OR EXCEED UL94-V0 REQUIREMENTS." at 11361.01,2277.37 h60
  text "PCB MUST BEAR THE UL94V-0 UL REGISTERED MATERIAL ID NUMBER" at 11361.01,2161.3 h60
  text "ADDITIONAL REQUIREMENTS:" at 11333.47,1991.88 h60
  text "MICROSECTION:" at 11408.23,1884.75 h60
  text "YES" at 12313.97,1884.75 h60
  text "REQUIRED" at 13175.47,1740.42 h60
  text "BARE BOARD ELEC. TEST:" at 11408.23,1737.56 h60
  text "NONE" at 12713.97,1737.56 h60
  text "X" at 13057.47,1737.56 h60
  text "PER ORDER" at 13767.47,1737.56 h60
  text "XX MIL VIAS REQUIRE NON-CONDUCTIVE FILL AND PLANARIZE" at 11576.38,1532.62 h59
  text "XX MIL VIAS REQUIRE CONDUCTIVE FILL AND PLANARIZE" at 11584.38,1428.64 h60
  text "X" at 11464.34,1267.79 h60
  text "OUTER XX MIL TRACES REQUIRE 50 OHM SINGLE-ENDED IMPEDANCE" at 11583.4,1265.26 h58
  text "LAYER 2 & 3 (INNER LAYERS) XX MIL WIDE, XX MIL SPACE / TRACES REQUIRE 100 OHM DIFFERENTIAL IMPEDANCE" at 11575.4,1029.54 h60
  text ".Layer_Name" at 577.01,-720.69 h60
M11 Gerber Information:
  lines w10: -291.99,-792.37 6308.01,-792.37 ; -291.99,-589.03 6310.01,-589.03 ; -291.99,-385.7 -291.99,-995.7 3713.01,-995.7 6310.01,-995.7 6310.01,-385.7 -291.49,-385.7 -291.49,-995.7 1284.01,-995.7 ; 2173.01,-995.7 2173.01,-385.7 ; 3440.01,-589.03 3440.01,-385.7 ; 4280.01,-589.03 4280.01,-385.7 ; 4902.01,-1002.2 4902.01,-799.37
  text "ALL ARTWORK VIEWED FROM TOP SIDE" at -228.49,-517.87 h60
  text "BOARD #:" at 2248.01,-517.87 h60
  text ".PRJ_Number" at 2793.51,-517.87 h60
  text "REV:" at 3638.01,-517.87 h60
  text ".PCB_Rev" at 3929.51,-517.87 h60
  text "SVN REV:" at 4476.01,-517.87 h60
  text ".VersionControl_RevNumber" at 4982.01,-517.87 h60
  text "LAYER NAME =" at -228.49,-720.69 h60
  text "TID #:" at 2248.01,-721.2 h60
  text ".TID" at 2793.51,-721.2 h60
  text "PLOT NAME =" at -228.49,-926.54 h60
  text ".plot_File_Name" at 577.01,-926.54 h60
  text "GENERATED    :" at 2250.01,-926.54 h60
  text ".Print_Date" at 3119.51,-926.54 h60
  text ".Print_Time" at 3848.51,-926.54 h60
  text "TEXAS INSTRUMENTS" at 5113.01,-926.54 h60
M12 Stackup:
  drawing of 305 lines, arcs and shapes, not listed
  text "THIS IS AN IMPEDANCE CONTROLLED BOARD." at 5594.06,5042.14 h100
  text "NOTE :" at 4913.01,4925.76 h80
  text "1. ALL CORE AND PREPREG THICKNESSES ARE UP TO FAB SHOP TO SELECT." at 4972.06,4798.43 h80
  text "2. EXTERNAL LAYER CU THICKNESSES ARE FINISHED THICKNESS AFTER PLATING." at 4972.06,4650.32 h80
  text "IMPEDANCE TABLE" at 6774.8,4270.96 h125
  text "LAYER NO" at 5262.05,3958.11 h70
  text "CONDUCTOR WIDTH" at 5929.05,3958.11 h70
  text "SPACING" at 7094.05,3958.11 h70
  text "IMPEDANCE +/- 10%" at 7726.05,3958.11 h70
  text "REFERENCE GND" at 8972.55,3958.11 h70
  text "1" at 5432.26,3691.48 h70
  text "50 OHMS" at 8038.76,3691.48 h70
  text "GND" at 9229.39,3691.48 h70
  text "10.25" at 6208.39,3688.15 h70
  text "15.5 mil" at 7113.42,3669.4 h70
  text "Layer" at 5623.63,1699.98 h60
  text "Name" at 6033.54,1699.98 h60
  text "Material" at 6963.29,1699.98 h60
  text "Thickness" at 7823.05,1699.98 h60
  text "Constant" at 8472.89,1699.98 h60
  text "Board Layer Stack" at 9042.75,1699.98 h60
  text "Top Overlay" at 6033.54,1579.98 h60
  text "Top Solder" at 6033.54,1459.98 h60
  text "Solder Resist" at 6963.29,1459.98 h60
  text "1.00mil" at 7823.05,1459.98 h60
  text "3.5" at 8472.89,1459.98 h60
  text "1" at 5623.63,1339.98 h60
  text "Top Layer" at 6033.54,1339.98 h60
  text "1.85mil" at 7823.05,1339.98 h60
  text "Dielectric 1" at 6033.54,1219.98 h60
  text "FR-4 High Tg" at 6963.29,1219.98 h60
  text "5.48mil" at 7823.05,1219.98 h60
  text "4.2" at 8472.89,1219.98 h60
  text "2" at 5623.63,1099.98 h60
  text "L02_GND" at 6033.54,1099.98 h60
  text "1.26mil" at 7823.05,1099.98 h60
  text "Dielectric1" at 6033.54,979.98 h60
  text "FR-4 High Tg" at 6963.29,979.98 h60
  text "42.82mil" at 7823.05,979.98 h60
  text "4.2" at 8472.89,979.98 h60
  text "3" at 5623.63,859.98 h60
  text "L03_PWR" at 6033.54,859.98 h60
  text "1.26mil" at 7823.05,859.98 h60
  text "Dielectric 2" at 6033.54,739.98 h60
  text "FR-4 High Tg" at 6963.29,739.98 h60
  text "5.48mil" at 7823.05,739.98 h60
  text "4.2" at 8472.89,739.98 h60
  text "4" at 5623.63,619.98 h60
  text "Bottom Layer" at 6033.54,619.98 h60
  text "1.85mil" at 7823.05,619.98 h60
  text "Bottom Solder" at 6033.54,499.98 h60
  text "Solder Resist" at 6963.29,499.98 h60
  text "1.00mil" at 7823.05,499.98 h60
  text "3.5" at 8472.89,499.98 h60
  text "Bottom Overlay" at 6033.54,379.98 h60
  text ".Layer_Name" at 577.01,-720.69 h60
M13 Component Bodies Top:
  text ".Layer_Name" at 577.01,-720.69 h60
M14 Component Bodies Bottom:
  text ".Layer_Name" at 577.01,-720.69 h60
M15 Courtyards Top:
  text ".Layer_Name" at 577.01,-720.69 h60
M16 Courtyards Bottom:
  text ".Layer_Name" at 577.01,-720.69 h60
Drill Drawing:
  circle w10: c5649.16,2436.1 r27.63
  lines w10: 5621.53,2159.83 5649.16,2173.65 5676.78,2159.83 5662.97,2187.46 5676.78,2215.09 5649.16,2201.27 5621.53,2215.09 5635.34,2187.46 5621.53,2159.83 ; 5621.53,2284.15 5676.78,2284.15 5676.78,2339.41 5621.53,2339.41 5621.53,2284.15 ; 5621.53,2588.05 5676.78,2588.05 5649.16,2532.79 5621.53,2588.05 ; 5621.53,2670.93 5635.34,2670.93 5649.16,2657.11 5662.97,2670.93 5676.78,2670.93 5662.97,2684.74 5676.78,2698.55 5662.97,2698.55 5649.16,2712.37 5635.34,2698.55 5621.53,2698.55 5635.34,2684.74 5621.53,2670.93 ; 5621.53,2781.43 5621.53,2795.25 5635.34,2809.06 5621.53,2822.87 5621.53,2836.69 5635.34,2836.69 5649.16,2822.87 5662.97,2836.69 5676.78,2836.69 5676.78,2822.87 5662.97,2809.06 5676.78,2795.25 5676.78,2781.43 5662.97,2781.43 5649.16,2795.25 5635.34,2781.43 5621.53,2781.43 ; 5621.53,2905.75 5676.78,2905.75 5676.78,2961.01 5621.53,2961.01 5621.53,2905.75 ; 5621.53,3057.7 5649.16,3030.07 5676.78,3057.7 5649.16,3085.33 5621.53,3057.7 ; 5621.53,3168.21 5635.34,3168.21 5635.34,3154.39 5662.97,3154.39 5662.97,3168.21 5676.78,3168.21 5676.78,3195.83 5662.97,3195.83 5662.97,3209.65 5635.34,3209.65 5635.34,3195.83 5621.53,3195.83 5621.53,3168.21 ; 5632.58,2295.2 5665.73,2295.2 5665.73,2328.36 5632.58,2328.36 5632.58,2295.2
  lines w12: 5571.44,2122.54 8802.93,2122.54 ; 5571.44,3241.42 8802.93,3241.42 ; 5909.3,1998.22 5909.3,3365.74 ; 6241.3,1998.22 6241.3,3365.74 ; 6877.87,1998.22 6877.87,3365.74 ; 7137.01,1998.22 7137.01,3365.74 ; 7512.16,1998.22 7512.16,3365.74 ; 8236.49,1998.22 8236.49,3365.74 ; 5571.44,1998.22 8802.93,1998.22 8802.93,3365.74 5571.44,3365.74 5571.44,1998.22
  text "Symbol" at 5646.03,3278.71 h72
  text "Quantity" at 5946.6,3278.71 h72
  text "Finished Hole Size" at 6278.6,3278.71 h72
  text "Plated" at 6915.16,3278.71 h72
  text "Hole Type" at 7174.3,3278.71 h72
  text "Drill Layer Pair" at 7549.46,3278.71 h72
  text "Hole Tolerance" at 8273.79,3278.71 h72
  text "6" at 5946.6,3154.39 h60
  text "35.43mil (0.900mm)" at 6278.6,3154.39 h60
  text "NPTH" at 6915.16,3154.39 h60
  text "Round" at 7174.3,3154.39 h60
  text "Top Layer - Bottom Layer" at 7549.46,3154.39 h60
  text "854" at 5946.6,3030.07 h60
  text "7.87mil (0.200mm)" at 6278.6,3030.07 h60
  text "PTH" at 6915.16,3030.07 h60
  text "Round" at 7174.3,3030.07 h60
  text "Top Layer - Bottom Layer" at 7549.46,3030.07 h60
  text "19" at 5946.6,2905.75 h60
  text "8.00mil (0.203mm)" at 6278.6,2905.75 h60
  text "PTH" at 6915.16,2905.75 h60
  text "Round" at 7174.3,2905.75 h60
  text "Top Layer - Bottom Layer" at 7549.46,2905.75 h60
  text "14" at 5946.6,2781.43 h60
  text "12.00mil (0.305mm)" at 6278.6,2781.43 h60
  text "PTH" at 6915.16,2781.43 h60
  text "Round" at 7174.3,2781.43 h60
  text "Top Layer - Bottom Layer" at 7549.46,2781.43 h60
  text "+0.00mil/-4.00mil" at 8273.79,2781.43 h60
  text "10" at 5946.6,2657.11 h60
  text "27.95mil (0.710mm)" at 6278.6,2657.11 h60
  text "PTH" at 6915.16,2657.11 h60
  text "Round" at 7174.3,2657.11 h60
  text "Top Layer - Bottom Layer" at 7549.46,2657.11 h60
  text "20" at 5946.6,2532.79 h60
  text "40.16mil (1.020mm)" at 6278.6,2532.79 h60
  text "PTH" at 6915.16,2532.79 h60
  text "Round" at 7174.3,2532.79 h60
  text "Top Layer - Bottom Layer" at 7549.46,2532.79 h60
  text "+/-7.87mil" at 8273.79,2532.79 h60
  text "40" at 5946.6,2408.47 h60
  text "40.16mil (1.020mm)" at 6278.6,2408.47 h60
  text "PTH" at 6915.16,2408.47 h60
  text "Round" at 7174.3,2408.47 h60
  text "Top Layer - Bottom Layer" at 7549.46,2408.47 h60
  text "39" at 5946.6,2284.15 h60
  text "45.28mil (1.150mm)" at 6278.6,2284.15 h60
  text "PTH" at 6915.16,2284.15 h60
  text "Round" at 7174.3,2284.15 h60
  text "Top Layer - Bottom Layer" at 7549.46,2284.15 h60
  text "4" at 5946.6,2159.83 h60
  text "47.24mil (1.200mm)" at 6278.6,2159.83 h60
  text "PTH" at 6915.16,2159.83 h60
  text "Slot" at 7174.3,2159.83 h60
  text "Top Layer - Bottom Layer" at 7549.46,2159.83 h60
  text "1006 Total" at 5946.6,2035.51 h60
  text "Slot definitions :" at 5646.03,1948.49 h60
  text "Routed Path Length" at 6096.75,1948.49 h60
  text "= Calculated from tool start centre position to tool end centre position." at 6636.48,1948.49 h60
  text "Hole Length" at 6096.75,1898.76 h60
  text "= Routed Path Length + Tool Size = Slot length as defined in the PCB layout" at 6436.68,1898.76 h60
  text ".Layer_Name" at 577.01,-720.69 h60
M17 Embedded Cavity:
  text ".Layer_Name" at 577.01,-720.69 h60
M18 Embedded Assembly:
  text ".Layer_Name" at 577.01,-720.69 h60
M19 Embedded Keepout:
  text ".Layer_Name" at 577.01,-720.69 h60

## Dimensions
-4.58,2637.83 to 2304.73,2535.26 on M2 Board Dimensions
24.81,-5.03 to 20.89,2666.56 on M2 Board Dimensions
2519.69,-144.09 to 3519.69,-144.09 on M2 Board Dimensions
